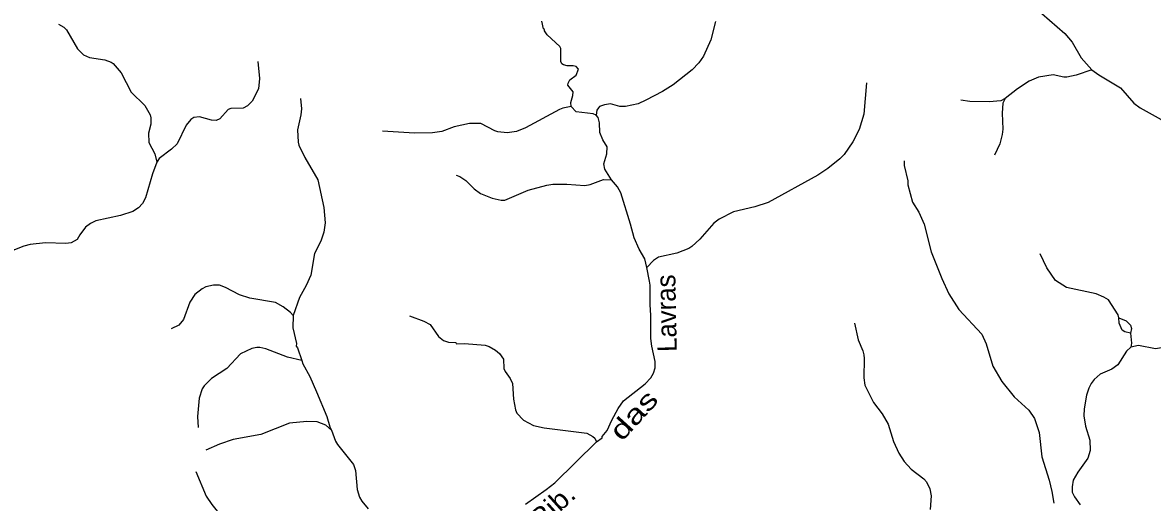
# Model space of a CAD drawing. Extents: x 346.5 to 372.4, y 7400.3 to 7428.2.
# Drawn here: x 351.415 to 356.096, y 7410.774 to 7412.763 of the extents above; entities that cross this region are included whole.
import ezdxf
from ezdxf.enums import TextEntityAlignment as Align

# ---------------------------------------------------------------- set-up
doc = ezdxf.new("R2010")
doc.units = 0
doc.header["$LTSCALE"] = 0.032
doc.layers.add('2', color=7, linetype='Continuous', lineweight=25)
doc.layers.add('7', color=7, linetype='Continuous', lineweight=25)
doc.layers.add('61', color=7, linetype='Continuous')

msp = doc.modelspace()

# ---------------------------------------------------------------- linework, layer by layer
at = {"layer": '2'}
msp.add_lwpolyline([(355.9579, 7411.5396), (355.9882, 7411.5268), (356.0055, 7411.5091), (356.0099, 7411.4952), (356.0051, 7411.4752), (355.9819, 7411.4805), (355.9713, 7411.4879), (355.959, 7411.5167)], close=True, dxfattribs=at)
at = {"layer": '7'}
for points in [[(355.3585, 7413.6889), (355.3504, 7413.6335), (355.3488, 7413.5538), (355.3528, 7413.5028), (355.3656, 7413.439), (355.3711, 7413.388), (355.3719, 7413.3625), (355.3648, 7413.286), (355.3719, 7413.1968), (355.3871, 7413.1553), (355.4389, 7413.1027), (355.4564, 7413.0772), (355.4739, 7413.039), (355.4931, 7412.9752), (355.5138, 7412.9242), (355.5321, 7412.886), (355.5552, 7412.8613), (355.572, 7412.8485), (355.6381, 7412.8007), (355.733, 7412.7186), (355.764, 7412.6827), (355.8015, 7412.6166), (355.8453, 7412.5673)], [(351.564, 7412.757), (351.5857, 7412.7449), (351.5968, 7412.733), (351.643, 7412.654), (351.6677, 7412.6293), (351.6917, 7412.619), (351.7554, 7412.6086), (351.7825, 7412.5998), (351.7897, 7412.5935), (351.8239, 7412.5544), (351.8646, 7412.4747), (351.922, 7412.419), (351.9435, 7412.3807), (351.9467, 7412.368), (351.9459, 7412.3425), (351.9363, 7412.3042), (351.9379, 7412.2659), (351.9626, 7412.2197), (351.9717, 7412.1845)], [(353.6885, 7412.416), (353.6872, 7412.4317), (353.6952, 7412.4604), (353.696, 7412.4763), (353.6744, 7412.5042), (353.6752, 7412.5122), (353.6832, 7412.5257), (353.7095, 7412.5457), (353.7183, 7412.5704), (353.7095, 7412.5807), (353.6968, 7412.5839), (353.6713, 7412.5839), (353.6561, 7412.5879), (353.6497, 7412.5927), (353.6458, 7412.6022), (353.6458, 7412.6556), (353.6418, 7412.6636), (353.5892, 7412.713), (353.578, 7412.729), (353.578, 7412.7345), (353.5732, 7412.7377), (353.5668, 7412.7698)], [(354.2857, 7412.768), (354.2674, 7412.6915), (354.2363, 7412.6246), (354.2164, 7412.5959), (354.1893, 7412.568), (354.1112, 7412.505), (354.0666, 7412.4779), (353.998, 7412.4421), (353.9653, 7412.4269), (353.9135, 7412.415), (353.8896, 7412.415), (353.8514, 7412.4261), (353.8259, 7412.4229), (353.806, 7412.415), (353.802, 7412.4102), (353.7941, 7412.3997), (353.7911, 7412.3801)], [(352.3898, 7412.6015), (352.3961, 7412.5321), (352.393, 7412.4883), (352.3659, 7412.4373), (352.3475, 7412.4181), (352.3292, 7412.4086), (352.2782, 7412.407), (352.2663, 7412.403), (352.2328, 7412.3647), (352.2176, 7412.3568), (352.1985, 7412.3584), (352.1475, 7412.3727), (352.1252, 7412.3695), (352.1116, 7412.3608), (352.0933, 7412.3377), (352.0551, 7412.2604), (352.032, 7412.238), (351.9805, 7412.1999), (351.9717, 7412.1845)], [(355.8453, 7412.5673), (355.78, 7412.5457), (355.7417, 7412.5369), (355.729, 7412.5369), (355.6851, 7412.5465), (355.6238, 7412.5377), (355.5855, 7412.5209), (355.5377, 7412.4891), (355.4857, 7412.4481)], [(355.8453, 7412.5673), (355.8748, 7412.5464), (355.9649, 7412.4923), (356.0191, 7412.4293), (356.0462, 7412.4102), (356.1322, 7412.3616), (356.1601, 7412.3385), (356.1864, 7412.309), (356.2191, 7412.2659), (356.2422, 7412.2229), (356.2693, 7412.1225), (356.2892, 7412.0635), (356.2988, 7412.0484), (356.3449, 7412.0009)], [(354.9113, 7412.5138), (354.9009, 7412.3839), (354.881, 7412.3201), (354.8555, 7412.2691), (354.8197, 7412.2157), (354.8013, 7412.1982), (354.7511, 7412.1583), (354.7097, 7412.1312), (354.5049, 7412.0173), (354.4491, 7411.999), (354.3614, 7411.9782), (354.3009, 7411.9479), (354.2793, 7411.932), (354.2219, 7411.8651), (354.1877, 7411.8348), (354.1757, 7411.8268), (354.1255, 7411.8077), (354.0506, 7411.7909), (354.0291, 7411.7774), (354.0017, 7411.7484)], [(352.5667, 7412.4484), (352.5707, 7412.4062), (352.5683, 7412.3807), (352.5539, 7412.3185), (352.5571, 7412.2675), (352.5603, 7412.2548), (352.5842, 7412.2038), (352.6384, 7412.1113), (352.6639, 7411.9966), (352.6687, 7411.9328), (352.6631, 7411.8946), (352.6504, 7411.8563), (352.6249, 7411.8053), (352.6097, 7411.7161), (352.5906, 7411.6738), (352.5627, 7411.6236), (352.5367, 7411.5484)], [(353.6885, 7412.416), (353.6534, 7412.409), (353.6394, 7412.403), (353.4991, 7412.3273), (353.4609, 7412.3122), (353.4226, 7412.3058), (353.3844, 7412.3098), (353.3716, 7412.3145), (353.3134, 7412.3448), (353.3047, 7412.3448), (353.2664, 7412.3448), (353.2027, 7412.3305), (353.1517, 7412.3122), (353.1134, 7412.3058), (353.0385, 7412.3042), (352.907, 7412.3138)], [(353.7911, 7412.3801), (353.7794, 7412.3849), (353.7095, 7412.3934), (353.6885, 7412.416)], [(355.4857, 7412.4481), (355.4683, 7412.4392), (355.4198, 7412.4349), (355.3401, 7412.4365), (355.3026, 7412.4421)], [(355.4857, 7412.4481), (355.4767, 7412.4295), (355.474, 7412.3871), (355.4771, 7412.3209), (355.474, 7412.2994), (355.4636, 7412.2612), (355.4421, 7412.2141)], [(353.8555, 7412.1114), (353.8275, 7412.156), (353.8235, 7412.1783), (353.8362, 7412.2197), (353.837, 7412.2484), (353.8195, 7412.2771), (353.8067, 7412.3082), (353.8059, 7412.3472), (353.8, 7412.3704), (353.7911, 7412.3801)], [(351.9717, 7412.1845), (351.9538, 7412.1368), (351.9243, 7412.0364), (351.9124, 7412.0133), (351.8949, 7411.995), (351.8718, 7411.9806), (351.8208, 7411.9631), (351.7188, 7411.9416), (351.6964, 7411.9304), (351.6757, 7411.9145), (351.6526, 7411.8826), (351.6407, 7411.8643), (351.6167, 7411.8507), (351.5944, 7411.8467), (351.51, 7411.8499), (351.4462, 7411.8428), (351.4207, 7411.8364), (351.3809, 7411.8204), (351.3251, 7411.7879)], [(355.0675, 7412.1902), (355.0683, 7412.1703), (355.0834, 7412.1066), (355.0834, 7412.0906), (355.1026, 7412.0189), (355.1281, 7411.9766), (355.1504, 7411.928), (355.1799, 7411.8133), (355.2237, 7411.7017), (355.2532, 7411.638), (355.2946, 7411.5742), (355.3895, 7411.4714), (355.407, 7411.4307), (355.4357, 7411.3383), (355.4724, 7411.2753), (355.5234, 7411.2108), (355.5839, 7411.1558), (355.6078, 7411.1215), (355.627, 7411.0642), (355.6389, 7410.9621), (355.6692, 7410.8665), (355.6796, 7410.8187), (355.6875, 7410.7709)], [(353.2114, 7412.1305), (353.2274, 7412.1257), (353.2513, 7412.1089), (353.2863, 7412.0739), (353.3118, 7412.0547), (353.3605, 7412.0348), (353.3987, 7412.0268), (353.4138, 7412.0268), (353.5103, 7412.0691), (353.5868, 7412.089), (353.6123, 7412.093), (353.6697, 7412.0938), (353.7446, 7412.0882), (353.7669, 7412.0914), (353.8227, 7412.1121), (353.8555, 7412.1114)], [(354.0017, 7411.7484), (353.9932, 7411.7838), (353.9701, 7411.8244), (353.9486, 7411.8707), (353.9342, 7411.928), (353.8944, 7412.0571), (353.88, 7412.0822), (353.8555, 7412.1114)], [(355.9579, 7411.5396), (355.9545, 7411.5513), (355.9139, 7411.6132), (355.8948, 7411.6252), (355.8629, 7411.6387), (355.7401, 7411.665), (355.6947, 7411.6945), (355.6596, 7411.7463), (355.6318, 7411.8045)], [(353.7931, 7411.0249), (353.8162, 7411.0419), (353.8163, 7411.0474), (353.8378, 7411.0713), (353.8561, 7411.1152), (353.8824, 7411.163), (353.9055, 7411.1948), (353.9948, 7411.2658), (354.0179, 7411.2905), (354.0291, 7411.3096), (354.0363, 7411.3311), (354.0355, 7411.3574), (354.0219, 7411.4212), (354.0187, 7411.4531), (354.0187, 7411.5487), (354.0155, 7411.5949), (354.0155, 7411.6746), (354.0123, 7411.6905), (354.0017, 7411.7484)], [(352.5367, 7411.5484), (352.525, 7411.5615), (352.495, 7411.5853), (352.4631, 7411.6029), (352.3563, 7411.6212), (352.3133, 7411.634), (352.2559, 7411.665), (352.2304, 7411.6746), (352.2065, 7411.6746), (352.1746, 7411.6674), (352.1587, 7411.6595), (352.1292, 7411.6356), (352.1084, 7411.6045), (352.0814, 7411.5328), (352.0622, 7411.508), (352.0304, 7411.4937)], [(356.3442, 7411.5746), (356.3299, 7411.5582), (356.3044, 7411.5415), (356.2582, 7411.5367), (356.2366, 7411.5144), (356.2039, 7411.469), (356.1721, 7411.4475), (356.1346, 7411.414), (356.1099, 7411.41), (356.0382, 7411.4243), (356.0076, 7411.4178)], [(352.5367, 7411.5484), (352.5348, 7411.4977), (352.55, 7411.4323), (352.5491, 7411.4212), (352.5547, 7411.4148), (352.5725, 7411.3618)], [(353.0186, 7411.5471), (353.0783, 7411.5256), (353.1038, 7411.5112), (353.1381, 7411.4618), (353.1596, 7411.4451), (353.1804, 7411.4379), (353.2098, 7411.4363), (353.2122, 7411.4315), (353.2457, 7411.4331), (353.3318, 7411.4259), (353.3485, 7411.4204), (353.3748, 7411.4052), (353.3907, 7411.3909), (353.4083, 7411.367), (353.4091, 7411.3287), (353.4146, 7411.316), (353.4354, 7411.2873), (353.4449, 7411.2674), (353.4489, 7411.2012), (353.4569, 7411.1582), (353.4625, 7411.1438), (353.4903, 7411.1151), (353.5326, 7411.0928), (353.5756, 7411.0825), (353.7526, 7411.0602), (353.7781, 7411.0474), (353.7867, 7411.0396), (353.7931, 7411.0249)], [(354.8619, 7411.5176), (354.8778, 7411.4483), (354.897, 7411.4021), (354.9002, 7411.3861), (354.9025, 7411.3702), (354.9002, 7411.2905), (354.9049, 7411.2602), (354.9408, 7411.1885), (354.9767, 7411.1407), (355.0014, 7411.0976), (355.0237, 7411.0259), (355.0452, 7410.9781), (355.0683, 7410.943), (355.097, 7410.9119), (355.1488, 7410.8721), (355.1607, 7410.8585), (355.1743, 7410.8298), (355.1791, 7410.8012), (355.1759, 7410.7438)], [(356.0051, 7411.4752), (356.0104, 7411.4335), (356.0076, 7411.4178)], [(352.5725, 7411.3618), (352.5125, 7411.3757), (352.4233, 7411.41), (352.3978, 7411.4156), (352.385, 7411.4164), (352.3643, 7411.4116), (352.3181, 7411.3893), (352.2607, 7411.3295), (352.1977, 7411.2873), (352.1674, 7411.257), (352.1587, 7411.2443), (352.1467, 7411.206), (352.1403, 7411.1295), (352.1427, 7411.0841)], [(356.0076, 7411.4178), (355.9888, 7411.4012), (355.9537, 7411.3447), (355.9282, 7411.3263), (355.8804, 7411.3056), (355.8557, 7411.2833), (355.8429, 7411.2674), (355.8326, 7411.2474), (355.823, 7411.2188), (355.8134, 7411.1614), (355.8119, 7411.1327), (355.8198, 7411.0897), (355.8374, 7411.0323), (355.8382, 7410.9892), (355.8294, 7410.9574), (355.7871, 7410.8984), (355.7688, 7410.8665), (355.764, 7410.8378), (355.764, 7410.8155), (355.7736, 7410.7964), (355.7975, 7410.7637)], [(352.5725, 7411.3618), (352.5769, 7411.3483), (352.6049, 7411.2953), (352.6328, 7411.2315), (352.6751, 7411.1295), (352.6875, 7411.0875), (352.6944, 7411.0737)], [(352.6944, 7411.0737), (352.6718, 7411.094), (352.6352, 7411.1072), (352.5922, 7411.1088), (352.5205, 7411.1016), (352.4025, 7411.0554), (352.2878, 7411.0346), (352.2304, 7411.0147), (352.1742, 7410.99)], [(352.6944, 7411.0737), (352.7117, 7411.0275), (352.7205, 7411.0131), (352.7867, 7410.9311), (352.7938, 7410.9064), (352.801, 7410.8267), (352.8113, 7410.7948), (352.8201, 7410.7788), (352.8464, 7410.747)], [(353.4983, 7410.7669), (353.5852, 7410.8266), (353.6202, 7410.8553), (353.7931, 7411.0249)], [(352.1332, 7410.9024), (352.1754, 7410.7996), (352.1993, 7410.7653), (352.2391, 7410.7151), (352.3212, 7410.6338), (352.3706, 7410.5756), (352.4049, 7410.5445), (352.4663, 7410.5039), (352.6297, 7410.3788), (352.7056, 7410.3052)]]:
    msp.add_lwpolyline(points, dxfattribs=at)

# ---------------------------------------------------------------- texts
at = {"layer": '61'}
msp.add_text('Lavras', height=0.08, rotation=91.193, dxfattribs=at).set_placement((354.1227, 7411.5588), align=Align.CENTER)
for s, rotation, width, p in [('das', 47.679, 1.35, (353.9767, 7411.1093)), ('Rib.', 41.922, 1.1, (353.6358, 7410.7276))]:
    msp.add_text(s, height=0.08, rotation=rotation, dxfattribs=dict(at, width=width)).set_placement(p, align=Align.CENTER)

doc.saveas('drawing.dxf')
